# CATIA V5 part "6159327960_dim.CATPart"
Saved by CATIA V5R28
Part number: 6159327960_dim
Source: made
Property "PROI_CREATED_ON": "12/17/2008 9:21:37 AM"
Property "BLANK_DRAWING": "--"
Property "DRAWN_BY": "FPA"
Property "FINISH": "--"
Property "HEAT_TREATMENT": "ASSIGN"
Property "MATERIAL": "ASSIGN"
Property "PROJECT": "--"
Property "PROTOTYPE_NO": "--"
Property "RELATED_DRAWING": "--"
Property "COMPLETE_MATERIAL": "ASSIGN-ASSIGN"
Property "DESCRIPTION": "AXD + AXM-SX Premium"
Property "DRAWING_EXIST": "--"
Property "MANUFACTURER": "--"
Property "MANUFACTURER_2": "--"
Property "MANUFACTURER_REF": "--"
Property "TYPE_PART": "--"
Property "TODAY_DATE": "2026/03/23"
Property "PDMREV": "01.0"
Property "PDMRL": "Production"
Property "PROI_REVISION": "01"
Property "PROI_VERSION": "0"
Property "PROI_RELEASE": "Production"
Property "PTC_MODIFIED": false
Property "MFG_WP_MATERIAL": "ASSIGN"
Property "COMPANY_CODE": "---"
Property "DESCRIPTION_JP": "--"
Property "PQP_DOCUMENT": "--"
Property "GHOST": false
Property "NO_PART": false
Property "REFERENCE": "6159327950_DIM"
Property "PTC_WM_ITERATION": "0"
Property "PTC_WM_VERSION": "01.0"
Property "PTC_WM_CREATED_ON": "24-Mar-26 09:23:24 AM"
Property "PTC_WM_MODIFIED_ON": "24-Mar-26 09:23:24 AM"
Property "PTC_WM_NAME": "6159327960_dim.prt"
Property "PTC_WM_NUMBER": "6159327960_DIM.PRT"
Property "PTC_WM_LIFECYCLE_STATE": "Production"
Property "PTC_WM_LIFECYCLE": "Design_Process"
Property "PTC_WM_REVISION": "01"
Property "PTC_WM_CREATED_BY": "Florian Pavageau (Grefpav) (Grefpav: CPD)"
Property "PTC_WM_MODIFIED_BY": "Florian Pavageau (Grefpav) (Grefpav: CPD)"
Property "PTC_ORGANIZATION_ID": "CPD"
Property "PTC_WM_TEAM": "Default"
Property "PTC_WM_LOCATION": "/Products/CONTROLLERS/A1770 - CX4 - SMART DRIVE - LEAN/9-01-Dimensional Drawings"
Property "PTC_WM_PART_NAME": "6159327960_dim"
Property "PTC_WM_PART_NUMBER": "6159327960_DIM"
Property "PTC_COMMON_NAME": "6159327960_dim.prt"
Property "PTC_MASTER_MATERIAL": "ASSIGN"
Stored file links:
  d:\ptc\Echange\temp\6159327960_dim.CATPart

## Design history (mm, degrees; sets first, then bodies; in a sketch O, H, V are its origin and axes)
AxisSystem1 "CS0": origin (0, 0, 0), X (1, 0, 0), Y (0, 1, 0), Z (0, 0, 1)
Set1
  DatumSurface1 "Sheet.1"
  DatumSurface2 "Sheet.2"
  DatumSurface3 "Sheet.3"
  DatumSurface4 "Sheet.4"
  DatumSurface5 "Sheet.5"
  DatumSurface6 "Sheet.6"
  DatumSurface7 "Sheet.7"
  DatumSurface8 "Sheet.8"
  DatumSurface9 "Sheet.9"
  DatumSurface10 "Sheet.10"
  DatumSurface11 "Sheet.11"
  DatumSurface12 "Sheet.12"
  DatumSurface13 "Sheet.13"
  DatumSurface14 "Sheet.14"
  DatumSurface15 "Sheet.15"
  DatumSurface16 "Sheet.16"
  DatumSurface17 "Sheet.17"
  DatumSurface18 "Sheet.18"
  DatumSurface19 "Sheet.19"
  DatumSurface20 "Sheet.20"
  DatumSurface21 "Sheet.21"
  DatumSurface22 "Sheet.22"
  DatumSurface23 "Sheet.23"
  DatumSurface24 "Sheet.24"
  DatumSurface25 "Sheet.25"
  DatumSurface26 "Sheet.26"
  DatumSurface27 "Sheet.27"
  DatumSurface28 "Sheet.28"
  DatumSurface29 "Sheet.29"
  DatumSurface30 "Sheet.30"
  DatumSurface31 "Sheet.31"
  DatumSurface32 "Sheet.32"
  DatumSurface33 "Sheet.33"
  DatumSurface34 "Sheet.34"
  DatumSurface35 "Sheet.35"
  DatumSurface36 "Sheet.36"
  DatumSurface37 "Sheet.37"
  DatumSurface38 "Sheet.38"
  DatumSurface39 "Sheet.39"
  DatumSurface40 "Sheet.40"
  DatumSurface41 "Sheet.41"
  DatumSurface42 "Sheet.42"
  DatumSurface43 "Sheet.43"
  DatumSurface44 "Sheet.44"
  DatumSurface45 "Sheet.45"
  DatumSurface46 "Sheet.46"
  DatumSurface47 "Sheet.47"
  DatumSurface48 "Sheet.48"
  DatumSurface49 "Sheet.49"
  DatumSurface50 "Sheet.50"
  DatumSurface51 "Sheet.51"
  DatumSurface52 "Sheet.52"
  DatumSurface53 "Sheet.53"
  DatumSurface54 "Sheet.54"
  DatumSurface55 "Sheet.55"
  DatumSurface56 "Sheet.56"
  DatumSurface57 "Sheet.57"
  DatumSurface58 "Sheet.58"
  DatumSurface59 "Sheet.59"
  DatumSurface60 "Sheet.60"
  DatumSurface61 "Sheet.61"
  DatumSurface62 "Sheet.62"
  DatumSurface63 "Sheet.63"
  DatumSurface64 "Sheet.64"
  DatumSurface65 "Sheet.65"
  DatumSurface66 "Sheet.66"
  DatumSurface67 "Sheet.67"
  DatumSurface68 "Sheet.68"
  DatumSurface69 "Sheet.69"
  DatumSurface70 "Sheet.70"
  DatumSurface71 "Sheet.71"
  DatumSurface72 "Sheet.72"
  DatumSurface73 "Sheet.73"
  DatumSurface74 "Sheet.74"
  DatumSurface75 "Sheet.75"
  DatumSurface76 "Sheet.76"
  DatumSurface77 "Sheet.77"
  DatumSurface78 "Sheet.78"
  DatumSurface79 "Sheet.79"
  DatumSurface80 "Sheet.80"
  DatumSurface81 "Sheet.81"
  DatumSurface82 "Sheet.82"
  DatumSurface83 "Sheet.83"
  DatumSurface84 "Sheet.84"
  DatumSurface85 "Sheet.85"
  DatumSurface86 "Sheet.86"
  DatumSurface87 "Sheet.87"
  DatumSurface88 "Sheet.88"
  DatumSurface89 "Sheet.89"
  DatumSurface90 "Sheet.90"
  DatumSurface91 "Sheet.91"
  DatumSurface92 "Sheet.92"
  DatumSurface93 "Sheet.93"
  DatumSurface94 "Sheet.94"
  DatumSurface95 "Sheet.95"
  DatumSurface96 "Sheet.96"
  DatumSurface97 "Sheet.97"
  DatumSurface98 "Sheet.98"
  DatumSurface99 "Sheet.99"
  DatumSurface100 "Sheet.100"
  DatumSurface101 "Sheet.101"
  DatumSurface102 "Sheet.102"
  DatumSurface103 "Sheet.103"
  DatumSurface104 "Sheet.104"
  DatumSurface105 "Sheet.105"
  DatumSurface106 "Sheet.106"
  DatumSurface107 "Sheet.107"
  DatumSurface108 "Sheet.108"
  DatumSurface109 "Sheet.109"
  DatumSurface110 "Sheet.110"
  DatumSurface111 "Sheet.111"
  DatumSurface112 "Sheet.112"
  DatumSurface113 "Sheet.113"
  DatumSurface114 "Sheet.114"
  DatumSurface115 "Sheet.115"
  DatumSurface116 "Sheet.116"
  DatumSurface117 "Sheet.117"
  DatumSurface118 "Sheet.118"
  DatumSurface119 "Sheet.119"
  DatumSurface120 "Sheet.120"
  DatumSurface121 "Sheet.121"
  DatumSurface122 "Sheet.122"
  DatumSurface123 "Sheet.123"
  DatumSurface124 "Sheet.124"
  DatumSurface125 "Sheet.125"
  DatumSurface126 "Sheet.126"
  DatumSurface127 "Sheet.127"
  DatumSurface128 "Sheet.128"
  DatumSurface129 "Sheet.129"
  DatumSurface130 "Sheet.130"
  DatumSurface131 "Sheet.131"
  DatumSurface132 "Sheet.132"
  DatumSurface133 "Sheet.133"
  DatumSurface134 "Sheet.134"
  DatumSurface135 "Sheet.135"
  DatumSurface136 "Sheet.136"
  DatumSurface137 "Sheet.137"
  DatumSurface138 "Sheet.138"
  DatumSurface139 "Sheet.139"
  DatumSurface140 "Sheet.140"
  DatumSurface141 "Sheet.141"
  DatumSurface142 "Sheet.142"
  DatumSurface143 "Sheet.143"
  DatumSurface144 "Sheet.144"
  DatumSurface145 "Sheet.145"
  DatumSurface146 "Sheet.146"
  DatumSurface147 "Sheet.147"
  DatumSurface148 "Sheet.148"
  DatumSurface149 "Sheet.149"
  DatumSurface150 "Sheet.150"
  DatumSurface151 "Sheet.151"
  DatumSurface152 "Sheet.152"
  DatumSurface153 "Sheet.153"
  DatumSurface154 "Sheet.154"
  DatumSurface155 "Sheet.155"
  DatumSurface156 "Sheet.156"
  DatumSurface157 "Sheet.157"
  DatumSurface158 "Sheet.158"
  DatumSurface159 "Sheet.159"
  DatumSurface160 "Sheet.160"
  DatumSurface161 "Sheet.161"
  DatumSurface162 "Sheet.162"
  DatumSurface163 "Sheet.163"
  DatumSurface164 "Sheet.164"
  DatumSurface165 "Sheet.165"
  DatumSurface166 "Sheet.166"
  DatumSurface167 "Sheet.167"
  DatumSurface168 "Sheet.168"
  DatumSurface169 "Sheet.169"
  DatumSurface170 "Sheet.170"
  DatumSurface171 "Sheet.171"
  DatumSurface172 "Sheet.172"
  DatumSurface173 "Sheet.173"
  DatumSurface174 "Sheet.174"
  DatumSurface175 "Sheet.175"
  DatumSurface176 "Sheet.176"
  DatumSurface177 "Sheet.177"
  DatumSurface178 "Sheet.178"
  DatumSurface179 "Sheet.179"
  DatumSurface180 "Sheet.180"
  DatumSurface181 "Sheet.181"
  DatumSurface182 "Sheet.182"
  DatumSurface183 "Sheet.183"
  DatumSurface184 "Sheet.184"
  DatumSurface185 "Sheet.185"
  DatumSurface186 "Sheet.186"
  DatumSurface187 "Sheet.187"
  DatumSurface188 "Sheet.188"
  DatumSurface189 "Sheet.189"
  DatumSurface190 "Sheet.190"
  DatumSurface191 "Sheet.191"
  DatumSurface192 "Sheet.192"
  DatumSurface193 "Sheet.193"
  DatumSurface194 "Sheet.194"
  DatumSurface195 "Sheet.195"
  DatumSurface196 "Sheet.196"
  DatumSurface197 "Sheet.197"
  DatumSurface198 "Sheet.198"
  DatumSurface199 "Sheet.199"
  DatumSurface200 "Sheet.200"
  DatumSurface201 "Sheet.201"
  DatumSurface202 "Sheet.202"
  DatumSurface203 "Sheet.203"
  DatumSurface204 "Sheet.204"
  DatumSurface205 "Sheet.205"
  DatumSurface206 "Sheet.206"
  DatumSurface207 "Sheet.207"
  DatumSurface208 "Sheet.208"
  DatumSurface209 "Sheet.209"
  DatumSurface210 "Sheet.210"
  DatumSurface211 "Sheet.211"
  DatumSurface212 "Sheet.212"
  DatumSurface213 "Sheet.213"
  DatumSurface214 "Sheet.214"
  DatumSurface215 "Sheet.215"
  DatumSurface216 "Sheet.216"
  DatumSurface217 "Sheet.217"
  DatumSurface218 "Sheet.218"
  DatumSurface219 "Sheet.219"
  DatumSurface220 "Sheet.220"
  DatumSurface221 "Sheet.221"
  DatumSurface222 "Sheet.222"
  DatumSurface223 "Sheet.223"
  DatumSurface224 "Sheet.224"
  DatumSurface225 "Sheet.225"
  DatumSurface226 "Sheet.226"
  DatumSurface227 "Sheet.227"
  DatumSurface228 "Sheet.228"
  DatumSurface229 "Sheet.229"
  DatumSurface230 "Sheet.230"
  DatumSurface231 "Sheet.231"
  DatumSurface232 "Sheet.232"
  DatumSurface233 "Sheet.233"
  DatumSurface234 "Sheet.234"
  DatumSurface235 "Sheet.235"
  DatumSurface236 "Sheet.236"
  DatumSurface237 "Sheet.237"
  DatumSurface238 "Sheet.238"
  DatumSurface239 "Sheet.239"
  DatumSurface240 "Sheet.240"
  DatumSurface241 "Sheet.241"
  DatumSurface242 "Sheet.242"
  DatumSurface243 "Sheet.243"
  DatumSurface244 "Sheet.244"
  DatumSurface245 "Sheet.245"
  DatumSurface246 "Sheet.246"
  DatumSurface247 "Sheet.247"
  DatumSurface248 "Sheet.248"
  DatumSurface249 "Sheet.249"
  DatumSurface250 "Sheet.250"
  DatumSurface251 "Sheet.251"
  DatumSurface252 "Sheet.252"
  DatumSurface253 "Sheet.253"
  DatumSurface254 "Sheet.254"
  DatumSurface255 "Sheet.255"
  DatumSurface256 "Sheet.256"
  DatumSurface257 "Sheet.257"
  DatumSurface258 "Sheet.258"
  DatumSurface259 "Sheet.259"
  DatumSurface260 "Sheet.260"
  DatumSurface261 "Sheet.261"
  DatumSurface262 "Sheet.262"
  DatumSurface263 "Sheet.263"
  DatumSurface264 "Sheet.264"
  DatumSurface265 "Sheet.265"
  DatumSurface266 "Sheet.266"
  DatumSurface267 "Sheet.267"
  DatumSurface268 "Sheet.268"
  DatumSurface269 "Sheet.269"
  DatumSurface270 "Sheet.270"
  DatumSurface271 "Sheet.271"
  DatumSurface272 "Sheet.272"
  DatumSurface273 "Sheet.273"
  DatumSurface274 "Sheet.274"
  DatumSurface275 "Sheet.275"
  DatumSurface276 "Sheet.276"
  DatumSurface277 "Sheet.277"
  DatumSurface278 "Sheet.278"
  DatumSurface279 "Sheet.279"
  DatumSurface280 "Sheet.280"
  DatumSurface281 "Sheet.281"
  DatumSurface282 "Sheet.282"
  DatumSurface283 "Sheet.283"
  DatumSurface284 "Sheet.284"
  DatumSurface285 "Sheet.285"
  DatumSurface286 "Sheet.286"
  DatumSurface287 "Sheet.287"
  DatumSurface288 "Sheet.288"
  DatumSurface289 "Sheet.289"
  DatumSurface290 "Sheet.290"
  DatumSurface291 "Sheet.291"
  DatumSurface292 "Sheet.292"
  DatumSurface293 "Sheet.293"
  DatumSurface294 "Sheet.294"
  DatumSurface295 "Sheet.295"
  DatumSurface296 "Sheet.296"
  DatumSurface297 "Sheet.297"
  DatumSurface298 "Sheet.298"
  DatumSurface299 "Sheet.299"
  DatumSurface300 "Sheet.300"
  DatumSurface301 "Sheet.301"
  DatumSurface302 "Sheet.302"
  Plane1 "RIGHT": stored without definition
  Plane2 "TOP": stored without definition
  Plane3 "FRONT": stored without definition
  Line1 "A_1": stored without definition
  Line2 "A_2": stored without definition
  Line3 "A_3": stored without definition
  Line4 "A_4": stored without definition
Body1 "PartBody" (main body)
